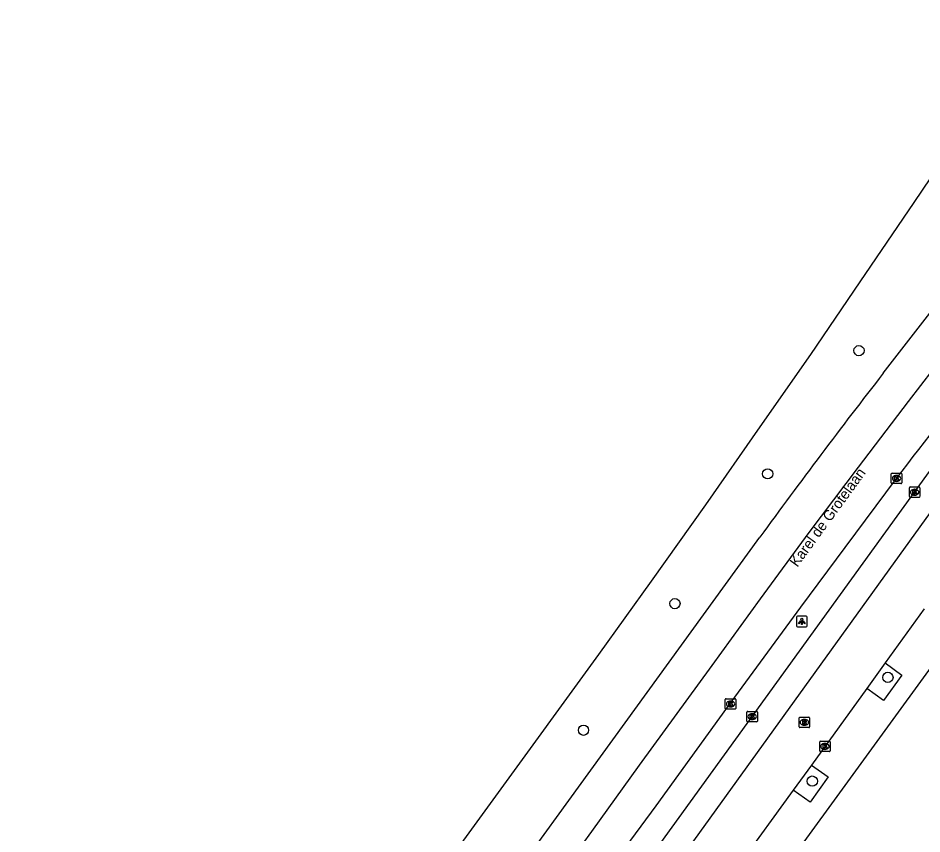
# Model space of a CAD drawing. Extents: x 160107 to 160928, y 382056 to 382918.
# Drawn here: x 160152.3 to 160238.7, y 382309.1 to 382387.1 of the extents above; entities that cross this region are included whole.
import ezdxf

# ---------------------------------------------------------------- set-up
doc = ezdxf.new("R2010")
doc.units = 0
for name, color, linetype in [('IMGEO_Boom', 7, 'Continuous'), ('IMGEO_Kolk', 7, 'Continuous'), ('IMGEO_Lichtpunt', 7, 'Continuous'), ('IMGEO_Openbare_ruimte_label', 7, 'Continuous'), ('IMGEO_Parkeervlak_open', 7, 'Continuous'), ('IMGEO_Rijbaan_lokaal_gesloten', 7, 'Continuous'), ('IMGEO_Rijbaan_lokaal_open', 7, 'Continuous'), ('IMGEO_Rioolput', 7, 'Continuous'), ('IMGEO_Voetpad_open', 7, 'Continuous')]:
    doc.layers.add(name, color=color, linetype=linetype)

msp = doc.modelspace()

# ---------------------------------------------------------------- linework, layer by layer
at = {"layer": 'IMGEO_Boom'}
for centre in [(160232.677, 382355.324), (160223.947, 382343.542), (160215.08, 382331.124), (160235.446, 382324.072), (160206.339, 382319.011), (160228.215, 382314.152)]:
    msp.add_circle(centre, 0.489, dxfattribs=at)
at = {"layer": 'IMGEO_Kolk'}
for p, q in [((160235.768, 382342.674), (160235.768, 382343.526)), ((160235.843, 382343.6), (160236.695, 382343.6)), ((160236.256, 382343.38), (160236.281, 382343.38)), ((160236.769, 382343.526), (160236.769, 382342.674)), ((160236.695, 382342.6), (160235.843, 382342.6)), ((160236.279, 382342.82), (160236.254, 382342.82)), ((160237.573, 382342.282), (160238.425, 382342.282)), ((160237.498, 382341.356), (160237.498, 382342.208)), ((160238.009, 382341.502), (160237.984, 382341.502)), ((160237.986, 382342.062), (160238.011, 382342.062)), ((160238.499, 382342.208), (160238.499, 382341.356)), ((160238.425, 382341.282), (160237.573, 382341.282)), ((160219.896, 382321.101), (160219.896, 382321.953)), ((160219.971, 382322.027), (160220.823, 382322.027)), ((160220.384, 382321.807), (160220.409, 382321.807)), ((160220.897, 382321.953), (160220.897, 382321.101)), ((160220.823, 382321.027), (160219.971, 382321.027)), ((160220.407, 382321.247), (160220.382, 382321.247)), ((160221.963, 382319.893), (160221.963, 382320.745)), ((160222.038, 382320.819), (160222.89, 382320.819)), ((160222.964, 382320.745), (160222.964, 382319.893)), ((160222.89, 382319.819), (160222.038, 382319.819)), ((160222.474, 382320.039), (160222.449, 382320.039)), ((160222.451, 382320.599), (160222.476, 382320.599)), ((160228.924, 382317.04), (160228.924, 382317.892)), ((160228.999, 382317.966), (160229.851, 382317.966)), ((160229.435, 382317.186), (160229.41, 382317.186)), ((160229.412, 382317.746), (160229.437, 382317.746)), ((160229.925, 382317.892), (160229.925, 382317.04)), ((160229.851, 382316.966), (160228.999, 382316.966))]:
    msp.add_line(p, q, dxfattribs=at)
for points in [[(160235.768, 382342.674), (160235.768, 382343.526)], [(160235.843, 382343.6), (160236.695, 382343.6)], [(160236.089, 382343.3), (160236.212, 382343.3), (160236.212, 382343.149), (160236.342, 382343.3), (160236.506, 382343.3), (160236.36, 382343.149), (160236.513, 382342.9), (160236.361, 382342.9), (160236.276, 382343.064), (160236.212, 382342.997), (160236.212, 382342.9), (160236.089, 382342.9), (160236.089, 382343.3)], [(160236.769, 382343.526), (160236.769, 382342.674)], [(160236.695, 382342.6), (160235.843, 382342.6)], [(160237.573, 382342.282), (160238.425, 382342.282)], [(160237.498, 382341.356), (160237.498, 382342.208)], [(160237.819, 382341.982), (160237.942, 382341.982), (160237.942, 382341.831), (160238.072, 382341.982), (160238.236, 382341.982), (160238.09, 382341.831), (160238.243, 382341.582), (160238.091, 382341.582), (160238.006, 382341.746), (160237.942, 382341.679), (160237.942, 382341.582), (160237.819, 382341.582), (160237.819, 382341.982)], [(160238.499, 382342.208), (160238.499, 382341.356)], [(160238.425, 382341.282), (160237.573, 382341.282)], [(160219.896, 382321.101), (160219.896, 382321.953)], [(160219.971, 382322.027), (160220.823, 382322.027)], [(160220.217, 382321.727), (160220.34, 382321.727), (160220.34, 382321.576), (160220.47, 382321.727), (160220.634, 382321.727), (160220.488, 382321.576), (160220.641, 382321.327), (160220.489, 382321.327), (160220.404, 382321.491), (160220.34, 382321.424), (160220.34, 382321.327), (160220.217, 382321.327), (160220.217, 382321.727)], [(160220.897, 382321.953), (160220.897, 382321.101)], [(160220.823, 382321.027), (160219.971, 382321.027)], [(160221.963, 382319.893), (160221.963, 382320.745)], [(160222.038, 382320.819), (160222.89, 382320.819)], [(160222.964, 382320.745), (160222.964, 382319.893)], [(160222.89, 382319.819), (160222.038, 382319.819)], [(160222.284, 382320.519), (160222.407, 382320.519), (160222.407, 382320.368), (160222.537, 382320.519), (160222.701, 382320.519), (160222.555, 382320.368), (160222.708, 382320.119), (160222.556, 382320.119), (160222.471, 382320.283), (160222.407, 382320.216), (160222.407, 382320.119), (160222.284, 382320.119), (160222.284, 382320.519)], [(160228.924, 382317.04), (160228.924, 382317.892)], [(160228.999, 382317.966), (160229.851, 382317.966)], [(160229.245, 382317.666), (160229.368, 382317.666), (160229.368, 382317.515), (160229.498, 382317.666), (160229.662, 382317.666), (160229.516, 382317.515), (160229.669, 382317.266), (160229.517, 382317.266), (160229.432, 382317.43), (160229.368, 382317.363), (160229.368, 382317.266), (160229.245, 382317.266), (160229.245, 382317.666)], [(160229.925, 382317.892), (160229.925, 382317.04)], [(160229.851, 382316.966), (160228.999, 382316.966)]]:
    msp.add_lwpolyline(points, dxfattribs=at)
for centre, start, end in [((160235.845, 382343.524), 91.55205, 178.44795), ((160235.845, 382343.524), 91.55205, 178.44795), ((160236.693, 382343.524), 1.55205, 88.44795), ((160236.693, 382343.524), 1.55205, 88.44795), ((160235.845, 382342.676), 181.55205, 268.44795), ((160235.845, 382342.676), 181.55205, 268.44795), ((160236.693, 382342.676), 271.55205, 358.44795), ((160236.693, 382342.676), 271.55205, 358.44795), ((160237.575, 382342.206), 91.55205, 178.44795), ((160237.575, 382342.206), 91.55205, 178.44795), ((160238.423, 382342.206), 1.55205, 88.44795), ((160238.423, 382342.206), 1.55205, 88.44795), ((160237.575, 382341.358), 181.55205, 268.44795), ((160237.575, 382341.358), 181.55205, 268.44795), ((160238.423, 382341.358), 271.55205, 358.44795), ((160238.423, 382341.358), 271.55205, 358.44795), ((160219.973, 382321.951), 91.55205, 178.44795), ((160219.973, 382321.951), 91.55205, 178.44795), ((160220.821, 382321.951), 1.55205, 88.44795), ((160220.821, 382321.951), 1.55205, 88.44795), ((160219.973, 382321.103), 181.55205, 268.44795), ((160219.973, 382321.103), 181.55205, 268.44795), ((160220.821, 382321.103), 271.55205, 358.44795), ((160220.821, 382321.103), 271.55205, 358.44795), ((160222.04, 382320.743), 91.55205, 178.44795), ((160222.04, 382320.743), 91.55205, 178.44795), ((160222.888, 382320.743), 1.55205, 88.44795), ((160222.888, 382320.743), 1.55205, 88.44795), ((160222.04, 382319.895), 181.55205, 268.44795), ((160222.04, 382319.895), 181.55205, 268.44795), ((160222.888, 382319.895), 271.55205, 358.44795), ((160222.888, 382319.895), 271.55205, 358.44795), ((160229.001, 382317.89), 91.55205, 178.44795), ((160229.001, 382317.89), 91.55205, 178.44795), ((160229.849, 382317.89), 1.55205, 88.44795), ((160229.849, 382317.89), 1.55205, 88.44795), ((160229.001, 382317.042), 181.55205, 268.44795), ((160229.001, 382317.042), 181.55205, 268.44795), ((160229.849, 382317.042), 271.55205, 358.44795), ((160229.849, 382317.042), 271.55205, 358.44795)]:
    msp.add_arc(centre, 0.0765, start, end, dxfattribs=at)
for centre, major_axis, ratio, start_param, end_param in [((160236.255, 382343.1), (-0.387, 0.002), 0.722429, 4.712389, 7.853982), ((160236.28, 382343.1), (-0.39, 0.002), 0.717154, 1.570796, 4.712389), ((160237.985, 382341.782), (-0.387, 0.002), 0.722429, 4.712389, 7.853982), ((160238.01, 382341.782), (-0.39, 0.002), 0.717154, 1.570796, 4.712389), ((160220.383, 382321.527), (-0.387, 0.002), 0.722429, 4.712389, 7.853982), ((160220.408, 382321.527), (-0.39, 0.002), 0.717154, 1.570796, 4.712389), ((160222.45, 382320.319), (-0.387, 0.002), 0.722429, 4.712389, 7.853982), ((160222.475, 382320.319), (-0.39, 0.002), 0.717154, 1.570796, 4.712389), ((160229.411, 382317.466), (-0.387, 0.002), 0.722429, 4.712389, 7.853982), ((160229.436, 382317.466), (-0.39, 0.002), 0.717154, 1.570796, 4.712389)]:
    msp.add_ellipse(centre, major_axis=major_axis, ratio=ratio, start_param=start_param, end_param=end_param, dxfattribs=at)
at = {"layer": 'IMGEO_Lichtpunt'}
for p, q in [((160226.717, 382329.821), (160226.717, 382329.014)), ((160226.717, 382329.821), (160226.717, 382329.014)), ((160227.619, 382329.916), (160226.811, 382329.916)), ((160227.619, 382329.916), (160226.811, 382329.916)), ((160227.713, 382329.014), (160227.713, 382329.821)), ((160227.713, 382329.014), (160227.713, 382329.821)), ((160226.811, 382328.92), (160227.619, 382328.92)), ((160226.811, 382328.92), (160227.619, 382328.92))]:
    msp.add_line(p, q, dxfattribs=at)
for points in [[(160227.091, 382329.485), (160227.13, 382329.457), (160226.942, 382329.195), (160226.904, 382329.222), (160227.091, 382329.485)], [(160227.193, 382329.437), (160227.24, 382329.437), (160227.24, 382329.115), (160227.193, 382329.115), (160227.193, 382329.437)], [(160227.303, 382329.457), (160227.341, 382329.484), (160227.528, 382329.222), (160227.489, 382329.194), (160227.303, 382329.457)]]:
    msp.add_lwpolyline(points, dxfattribs=at)
msp.add_circle((160227.216, 382329.619), 0.0994, dxfattribs=at)
for centre, start, end in [((160226.811, 382329.821), 90, 180), ((160226.811, 382329.821), 90, 180), ((160227.619, 382329.821), 0, 90), ((160227.619, 382329.821), 0, 90), ((160226.811, 382329.014), 180, 270), ((160226.811, 382329.014), 180, 270), ((160227.619, 382329.014), 270, 0), ((160227.619, 382329.014), 270, 360)]:
    msp.add_arc(centre, 0.0946, start, end, dxfattribs=at)
at = {"layer": 'IMGEO_Parkeervlak_open'}
msp.add_lwpolyline([(160211.552, 382305.243), (160247.438, 382354.824)], dxfattribs=at)
at = {"layer": 'IMGEO_Rijbaan_lokaal_gesloten'}
for points in [[(160152.266, 382250), (160153.158, 382251.113), (160178.492, 382285.961), (160207.787, 382326.257), (160212.852, 382333.289), (160218.035, 382340.57), (160223.233, 382348.042), (160228.076, 382354.969), (160232.786, 382361.903), (160237.958, 382369.491), (160241.999, 382375.5), (160249.716, 382387.135)], [(160234.997, 382353.157), (160239.884, 382359.495), (160244.492, 382365.391), (160257.39, 382381.679)], [(160242.092, 382356.587), (160237.376, 382350.447), (160232.607, 382344.177), (160227.875, 382337.913), (160223.234, 382331.571), (160218.617, 382325.198), (160211.655, 382315.684), (160207.086, 382309.322), (160202.467, 382302.938)], [(160209.603, 382306.625), (160209.748, 382306.955), (160210.855, 382308.487), (160213.286, 382311.771), (160220.447, 382321.689), (160227.125, 382330.799), (160231.36, 382336.509), (160236.263, 382343.1)], [(160157.826, 382247.361), (160159.74, 382250), (160183.373, 382282.577), (160223.206, 382337.486)]]:
    msp.add_lwpolyline(points, dxfattribs=at)
for centre, radius, start, end in [((159207.36, 383137.955), 1300.168, 322.312951, 322.931288), ((160696.988, 381993.28), 585.617, 142.082452, 144.001291)]:
    msp.add_arc(centre, radius, start, end, dxfattribs=at)
at = {"layer": 'IMGEO_Rijbaan_lokaal_open'}
for points in [[(160210.95, 382300.202), (160257.638, 382364.962)], [(160238.914, 382330.614), (160235.19, 382325.452)], [(160235.19, 382325.452), (160233.432, 382323.015)], [(160233.432, 382323.015), (160228.135, 382315.681)], [(160228.135, 382315.681), (160226.384, 382313.267)], [(160226.384, 382313.267), (160221.25, 382306.189)]]:
    msp.add_lwpolyline(points, dxfattribs=at)
at = {"layer": 'IMGEO_Rioolput'}
for p, q in [((160226.955, 382319.34), (160226.955, 382320.192)), ((160227.03, 382320.266), (160227.882, 382320.266)), ((160227.443, 382320.046), (160227.468, 382320.046)), ((160227.956, 382320.192), (160227.956, 382319.34)), ((160227.882, 382319.266), (160227.03, 382319.266)), ((160227.466, 382319.486), (160227.441, 382319.486))]:
    msp.add_line(p, q, dxfattribs=at)
for points in [[(160226.955, 382319.34), (160226.955, 382320.192)], [(160227.03, 382320.266), (160227.882, 382320.266)], [(160227.544, 382319.964), (160227.292, 382319.966), (160227.292, 382319.566)], [(160227.47, 382319.885), (160227.416, 382319.885), (160227.416, 382319.804)], [(160227.416, 382319.804), (160227.468, 382319.804)], [(160227.956, 382320.192), (160227.956, 382319.34)], [(160227.882, 382319.266), (160227.03, 382319.266)], [(160227.292, 382319.566), (160227.416, 382319.566), (160227.416, 382319.728), (160227.427, 382319.728)], [(160227.474, 382319.699), (160227.545, 382319.566), (160227.685, 382319.566), (160227.62, 382319.692)]]:
    msp.add_lwpolyline(points, dxfattribs=at)
for centre, radius, start, end in [((160227.032, 382320.19), 0.0765, 91.55205, 178.44795), ((160227.032, 382320.19), 0.0765, 91.55205, 178.44795), ((160227.452, 382319.993), 0.19, 274.7715, 282.96867), ((160227.476, 382319.789), 0.0964, 77.00612, 93.18647), ((160227.49, 382319.846), 0.0378, 276.66336, 79.67722), ((160227.543, 382319.854), 0.109, 350.36119, 89.41601), ((160227.541, 382319.854), 0.112, 277.58423, 350.98172), ((160227.88, 382320.19), 0.0765, 1.55205, 88.44795), ((160227.88, 382320.19), 0.0765, 1.55205, 88.44795), ((160227.032, 382319.342), 0.0765, 181.55205, 268.44795), ((160227.032, 382319.342), 0.0765, 181.55205, 268.44795), ((160227.426, 382319.675), 0.0533, 26.02933, 88.69889), ((160227.525, 382319.639), 0.108, 29.51342, 73.79051), ((160227.88, 382319.342), 0.0765, 271.55205, 358.44795), ((160227.88, 382319.342), 0.0765, 271.55205, 358.44795)]:
    msp.add_arc(centre, radius, start, end, dxfattribs=at)
for centre, major_axis, ratio, start_param, end_param in [((160227.442, 382319.766), (-0.387, 0.002), 0.722429, 4.712389, 7.853982), ((160227.467, 382319.766), (-0.39, 0.002), 0.717154, 1.570796, 4.712389)]:
    msp.add_ellipse(centre, major_axis=major_axis, ratio=ratio, start_param=start_param, end_param=end_param, dxfattribs=at)
at = {"layer": 'IMGEO_Voetpad_open'}
for points in [[(160265.62, 382360.89), (160225.112, 382305.189)], [(160235.19, 382325.452), (160236.784, 382324.287), (160235.011, 382321.861), (160233.432, 382323.015)], [(160228.135, 382315.681), (160229.725, 382314.553), (160227.999, 382312.121), (160226.384, 382313.267)]]:
    msp.add_lwpolyline(points, dxfattribs=at)

# ---------------------------------------------------------------- texts
at = {"layer": 'IMGEO_Openbare_ruimte_label'}
msp.add_text('Karel de Grotelaan', height=1, rotation=54.03584, dxfattribs=at).set_placement((160226.781, 382334.55))

doc.saveas('drawing.dxf')
